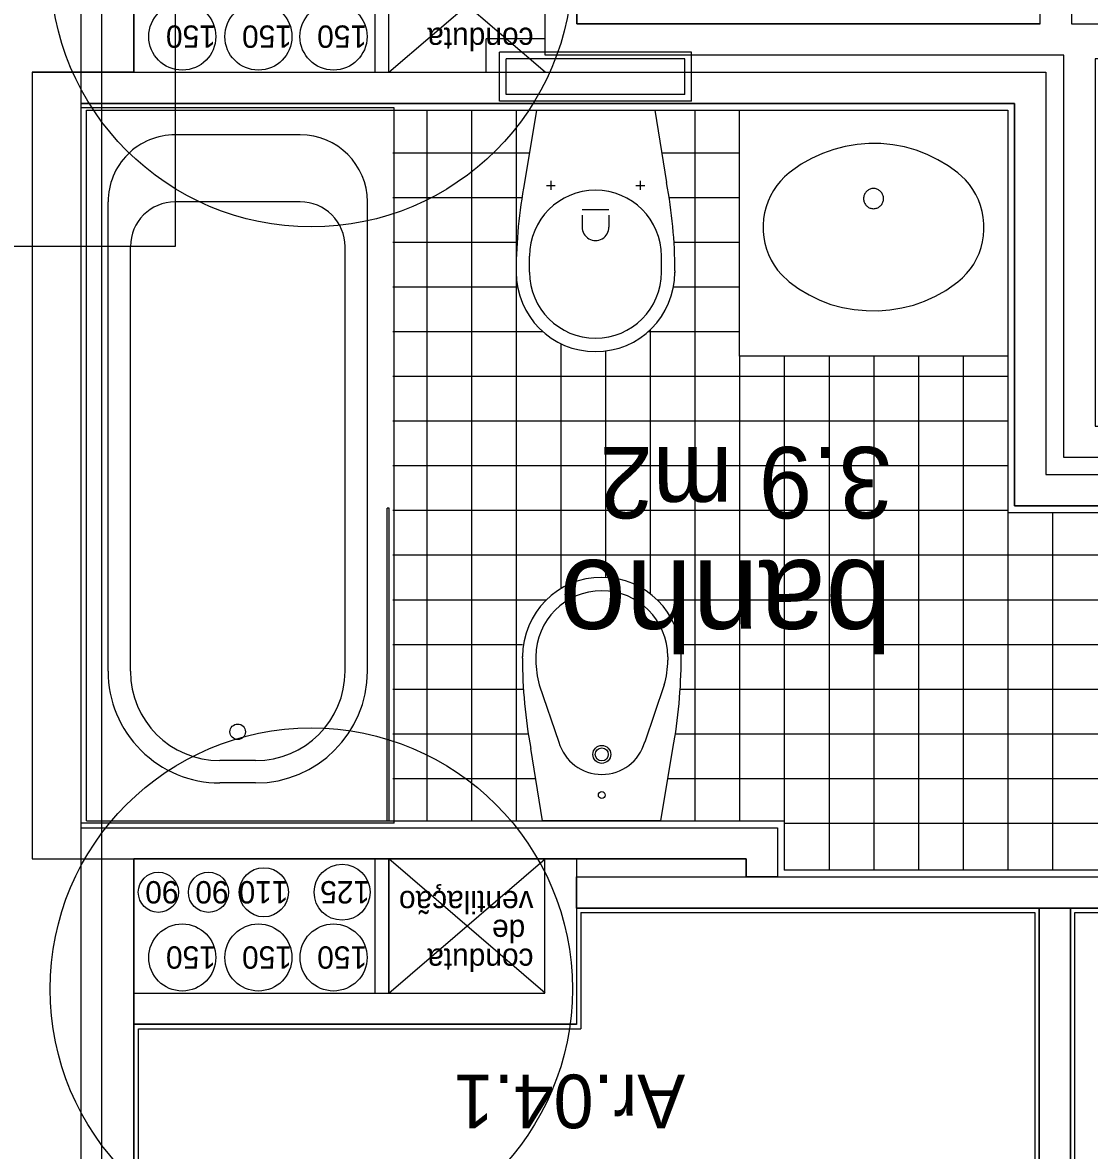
# Model space of a CAD drawing. Extents: x 1278 to 1356, y -253.7 to -224.
# Drawn here: x 1318.382 to 1320.769, y -240.956 to -238.433 of the extents above; entities that cross this region are included whole.
import ezdxf

# ---------------------------------------------------------------- set-up
doc = ezdxf.new("R2010")
doc.units = 0
for name, color, linetype in [('Level 1', 7, 'Continuous'), ('Level 10', 7, 'Continuous'), ('Level 11', 7, 'Continuous'), ('Level 2', 7, 'Continuous'), ('Level 36', 7, 'Continuous'), ('Level 40', 7, 'Continuous'), ('Level 41', 7, 'Continuous'), ('Level 60', 7, 'Continuous'), ('Level 65', 7, 'Continuous'), ('Level 66', 7, 'Continuous'), ('Level 67', 7, 'Continuous'), ('Level 69', 7, 'Continuous'), ('Level 70', 7, 'Continuous')]:
    doc.layers.add(name, color=color, linetype=linetype)

msp = doc.modelspace()

# ---------------------------------------------------------------- linework, layer by layer
at = {"layer": 'Level 1'}
for p, q in [((1320.6583, -238.4357), (1320.6583, -237.724)), ((1320.7283, -237.724), (1320.7283, -238.434)), ((1318.631, -238.544), (1318.631, -238.244)), ((1319.171, -238.544), (1319.171, -238.244)), ((1319.201, -238.544), (1319.201, -238.244)), ((1319.551, -238.499), (1319.551, -238.244)), ((1320.7283, -238.4357), (1320.8183, -238.4357)), ((1319.551, -238.469), (1319.4187, -238.469)), ((1319.551, -238.499), (1319.4487, -238.499)), ((1320.711, -238.5057), (1319.551, -238.5057)), ((1320.711, -239.4057), (1320.711, -238.5057)), ((1318.4033, -238.544), (1320.671, -238.544)), ((1320.671, -238.544), (1320.671, -239.444)), ((1318.5133, -238.614), (1320.601, -238.614)), ((1320.601, -238.614), (1320.601, -239.514)), ((1321.711, -239.4057), (1320.711, -239.4057)), ((1320.671, -239.444), (1321.671, -239.444)), ((1320.601, -239.514), (1321.601, -239.514)), ((1318.5133, -240.234), (1320.071, -240.234)), ((1320.071, -240.234), (1320.071, -240.344)), ((1318.4033, -240.304), (1319.5502, -240.304)), ((1318.631, -242.1713), (1318.631, -240.304)), ((1319.171, -240.604), (1319.171, -240.304)), ((1319.201, -240.604), (1319.201, -240.304)), ((1319.5502, -240.6039), (1319.5502, -240.3039)), ((1319.621, -240.304), (1320.001, -240.304)), ((1320.001, -240.304), (1320.001, -240.344)), ((1319.621, -240.414), (1320.656, -240.414)), ((1320.656, -240.414), (1320.656, -242.194)), ((1320.726, -242.194), (1320.726, -240.414)), ((1320.726, -240.414), (1320.836, -240.414)), ((1318.631, -240.6039), (1319.5502, -240.6039)), ((1318.6303, -240.6739), (1319.621, -240.6739))]:
    msp.add_line(p, q, dxfattribs=at)
for points in [[(1319.621, -240.304), (1319.621, -240.344)], [(1319.621, -240.414), (1319.621, -240.674)]]:
    msp.add_lwpolyline(points, dxfattribs=at)
at = {"layer": 'Level 10'}
for p, q in [((1319.286, -238.629), (1319.286, -240.219)), ((1319.386, -238.629), (1319.386, -240.219)), ((1319.486, -238.629), (1319.486, -240.219)), ((1319.886, -238.629), (1319.886, -240.219)), ((1319.2103, -238.724), (1319.5157, -238.724)), ((1319.8116, -238.724), (1319.986, -238.724)), ((1319.2103, -238.824), (1319.499, -238.824)), ((1319.8284, -238.824), (1319.986, -238.824)), ((1319.2103, -238.924), (1319.4882, -238.924)), ((1319.8393, -238.924), (1319.986, -238.924)), ((1319.2103, -239.024), (1319.4892, -239.024)), ((1319.8382, -239.024), (1319.986, -239.024)), ((1319.2103, -239.124), (1319.5456, -239.124)), ((1319.7818, -239.124), (1319.986, -239.124)), ((1319.786, -239.1201), (1319.786, -239.7109)), ((1319.586, -239.1511), (1319.586, -239.6995)), ((1319.686, -239.1676), (1319.686, -239.6742)), ((1319.986, -239.179), (1319.986, -240.219)), ((1320.086, -239.179), (1320.086, -240.219)), ((1320.186, -239.179), (1320.186, -240.329)), ((1320.286, -239.179), (1320.286, -240.329)), ((1320.386, -239.179), (1320.386, -240.329)), ((1320.486, -239.179), (1320.486, -240.329)), ((1319.2103, -239.224), (1320.586, -239.224)), ((1319.2103, -239.324), (1320.586, -239.324)), ((1319.2103, -239.424), (1320.586, -239.424)), ((1319.2103, -239.524), (1320.586, -239.524)), ((1320.586, -239.529), (1320.586, -240.329)), ((1320.686, -239.529), (1320.686, -240.329)), ((1319.2103, -239.624), (1321.586, -239.624)), ((1319.2103, -239.724), (1319.5542, -239.724)), ((1319.8012, -239.724), (1321.586, -239.724)), ((1319.2103, -239.824), (1319.5005, -239.824)), ((1319.8548, -239.824), (1321.496, -239.824)), ((1319.2103, -239.924), (1319.5024, -239.924)), ((1319.853, -239.924), (1321.496, -239.924)), ((1319.2103, -240.024), (1319.5132, -240.024)), ((1319.8422, -240.024), (1321.496, -240.024)), ((1319.2103, -240.124), (1319.5298, -240.124)), ((1319.8256, -240.124), (1321.496, -240.124)), ((1320.086, -240.224), (1321.496, -240.224))]:
    msp.add_line(p, q, dxfattribs=at)
at = {"layer": 'Level 11'}
for p, q in [((1319.4487, -238.609), (1319.4487, -238.499)), ((1319.8787, -238.499), (1319.4487, -238.499)), ((1319.8787, -238.609), (1319.8787, -238.499)), ((1319.8637, -238.514), (1319.4637, -238.514)), ((1319.4637, -238.594), (1319.4637, -238.514)), ((1319.8637, -238.594), (1319.8637, -238.514)), ((1319.8787, -238.609), (1319.4487, -238.609)), ((1319.8637, -238.594), (1319.4637, -238.594)), ((1319.2133, -238.624), (1318.5133, -238.624)), ((1318.5133, -240.224), (1318.5133, -238.624)), ((1319.2133, -240.224), (1319.2133, -238.624)), ((1319.5314, -238.629), (1319.5047, -238.791)), ((1319.5314, -238.629), (1319.796, -238.629)), ((1319.796, -238.629), (1319.8226, -238.791)), ((1319.0033, -238.684), (1318.7233, -238.684)), ((1320.2223, -238.7099), (1320.1965, -238.7166)), ((1320.2488, -238.7055), (1320.2223, -238.7099)), ((1320.2754, -238.7034), (1320.2488, -238.7055)), ((1320.3021, -238.7037), (1320.2754, -238.7034)), ((1320.3286, -238.7063), (1320.3021, -238.7037)), ((1320.3548, -238.7113), (1320.3286, -238.7063)), ((1320.3807, -238.7185), (1320.3548, -238.7113)), ((1320.147, -238.7367), (1320.1238, -238.75)), ((1320.1713, -238.7256), (1320.147, -238.7367)), ((1320.1965, -238.7166), (1320.1713, -238.7256)), ((1320.4057, -238.728), (1320.3807, -238.7185)), ((1320.4297, -238.7397), (1320.4057, -238.728)), ((1320.1238, -238.75), (1320.0967, -238.7691)), ((1320.4527, -238.7534), (1320.4297, -238.7397)), ((1320.4744, -238.7691), (1320.4527, -238.7534)), ((1319.5637, -238.7872), (1319.5637, -238.8072)), ((1319.7637, -238.7872), (1319.7637, -238.8072)), ((1320.0774, -238.7874), (1320.069, -238.7978)), ((1320.0867, -238.7779), (1320.0774, -238.7874)), ((1320.0967, -238.7691), (1320.0867, -238.7779)), ((1320.4916, -238.7851), (1320.4744, -238.7691)), ((1320.5002, -238.7953), (1320.4916, -238.7851)), ((1319.5537, -238.7972), (1319.5737, -238.7972)), ((1319.7537, -238.7972), (1319.7737, -238.7972)), ((1320.0615, -238.8089), (1320.055, -238.8206)), ((1320.069, -238.7978), (1320.0615, -238.8089)), ((1320.2685, -238.8122), (1320.2673, -238.8138)), ((1320.2698, -238.8108), (1320.2685, -238.8122)), ((1320.2712, -238.8095), (1320.2698, -238.8108)), ((1320.2728, -238.8083), (1320.2712, -238.8095)), ((1320.2744, -238.8072), (1320.2728, -238.8083)), ((1320.2761, -238.8063), (1320.2744, -238.8072)), ((1320.2779, -238.8055), (1320.2761, -238.8063)), ((1320.2798, -238.8049), (1320.2779, -238.8055)), ((1320.2817, -238.8045), (1320.2798, -238.8049)), ((1320.2836, -238.8043), (1320.2817, -238.8045)), ((1320.2855, -238.8042), (1320.2836, -238.8043)), ((1320.2875, -238.8043), (1320.2855, -238.8042)), ((1320.2894, -238.8045), (1320.2875, -238.8043)), ((1320.2913, -238.8049), (1320.2894, -238.8045)), ((1320.2932, -238.8055), (1320.2913, -238.8049)), ((1320.295, -238.8063), (1320.2932, -238.8055)), ((1320.2967, -238.8072), (1320.295, -238.8063)), ((1320.2983, -238.8083), (1320.2967, -238.8072)), ((1320.2999, -238.8095), (1320.2983, -238.8083)), ((1320.3013, -238.8108), (1320.2999, -238.8095)), ((1320.3026, -238.8122), (1320.3013, -238.8108)), ((1320.3038, -238.8138), (1320.3026, -238.8122)), ((1320.5079, -238.8062), (1320.5002, -238.7953)), ((1320.5147, -238.8177), (1320.5079, -238.8062)), ((1318.5733, -239.884), (1318.5733, -238.834)), ((1319.0033, -238.834), (1318.7233, -238.834)), ((1319.1533, -239.884), (1319.1533, -238.834)), ((1320.0495, -238.8328), (1320.0451, -238.8454)), ((1320.055, -238.8206), (1320.0495, -238.8328)), ((1320.2633, -238.8248), (1320.2632, -238.8267)), ((1320.2632, -238.8267), (1320.2633, -238.8287)), ((1320.2636, -238.8228), (1320.2633, -238.8248)), ((1320.2633, -238.8287), (1320.2636, -238.8307)), ((1320.264, -238.8209), (1320.2636, -238.8228)), ((1320.2636, -238.8307), (1320.264, -238.8326)), ((1320.2646, -238.819), (1320.264, -238.8209)), ((1320.264, -238.8326), (1320.2646, -238.8345)), ((1320.2653, -238.8172), (1320.2646, -238.819)), ((1320.2646, -238.8345), (1320.2653, -238.8363)), ((1320.2662, -238.8155), (1320.2653, -238.8172)), ((1320.2653, -238.8363), (1320.2662, -238.838)), ((1320.2673, -238.8138), (1320.2662, -238.8155)), ((1320.2662, -238.838), (1320.2673, -238.8397)), ((1320.3049, -238.8155), (1320.3038, -238.8138)), ((1320.3038, -238.8397), (1320.3049, -238.838)), ((1320.3058, -238.8172), (1320.3049, -238.8155)), ((1320.3049, -238.838), (1320.3058, -238.8363)), ((1320.3065, -238.819), (1320.3058, -238.8172)), ((1320.3058, -238.8363), (1320.3065, -238.8345)), ((1320.3071, -238.8209), (1320.3065, -238.819)), ((1320.3065, -238.8345), (1320.3071, -238.8326)), ((1320.3075, -238.8228), (1320.3071, -238.8209)), ((1320.3071, -238.8326), (1320.3075, -238.8307)), ((1320.3078, -238.8248), (1320.3075, -238.8228)), ((1320.3075, -238.8307), (1320.3078, -238.8287)), ((1320.3079, -238.8267), (1320.3078, -238.8248)), ((1320.3078, -238.8287), (1320.3079, -238.8267)), ((1320.5204, -238.8298), (1320.5147, -238.8177)), ((1320.5251, -238.8424), (1320.5204, -238.8298)), ((1319.6337, -238.8512), (1319.6937, -238.8512)), ((1319.6337, -238.8635), (1319.6337, -238.8907)), ((1319.6937, -238.8635), (1319.6937, -238.8907)), ((1320.0418, -238.8584), (1320.0396, -238.8716)), ((1320.0451, -238.8454), (1320.0418, -238.8584)), ((1320.2673, -238.8397), (1320.2685, -238.8412)), ((1320.2685, -238.8412), (1320.2698, -238.8427)), ((1320.2698, -238.8427), (1320.2712, -238.844)), ((1320.2712, -238.844), (1320.2728, -238.8452)), ((1320.2728, -238.8452), (1320.2744, -238.8463)), ((1320.2744, -238.8463), (1320.2761, -238.8472)), ((1320.2761, -238.8472), (1320.2779, -238.8479)), ((1320.2779, -238.8479), (1320.2798, -238.8485)), ((1320.2798, -238.8485), (1320.2817, -238.849)), ((1320.2817, -238.849), (1320.2836, -238.8492)), ((1320.2836, -238.8492), (1320.2855, -238.8493)), ((1320.2855, -238.8493), (1320.2875, -238.8492)), ((1320.2875, -238.8492), (1320.2894, -238.849)), ((1320.2894, -238.849), (1320.2913, -238.8485)), ((1320.2913, -238.8485), (1320.2932, -238.8479)), ((1320.2932, -238.8479), (1320.295, -238.8472)), ((1320.295, -238.8472), (1320.2967, -238.8463)), ((1320.2967, -238.8463), (1320.2983, -238.8452)), ((1320.2983, -238.8452), (1320.2999, -238.844)), ((1320.2999, -238.844), (1320.3013, -238.8427)), ((1320.3013, -238.8427), (1320.3026, -238.8412)), ((1320.3026, -238.8412), (1320.3038, -238.8397)), ((1320.5286, -238.8553), (1320.5251, -238.8424)), ((1320.5311, -238.8685), (1320.5286, -238.8553)), ((1320.0396, -238.8716), (1320.0386, -238.8863)), ((1320.0386, -238.8863), (1320.0387, -238.9001)), ((1320.5324, -238.8831), (1320.5311, -238.8685)), ((1320.5325, -238.8969), (1320.5324, -238.8831)), ((1320.0387, -238.9001), (1320.04, -238.9135)), ((1320.04, -238.9135), (1320.0425, -238.9267)), ((1320.5293, -238.9235), (1320.5315, -238.9103)), ((1320.5315, -238.9103), (1320.5325, -238.8969)), ((1318.6233, -239.884), (1318.6233, -238.934)), ((1319.1033, -239.884), (1319.1033, -238.934)), ((1320.0425, -238.9267), (1320.046, -238.9396)), ((1320.046, -238.9396), (1320.0507, -238.9521)), ((1320.5216, -238.9492), (1320.526, -238.9365)), ((1320.526, -238.9365), (1320.5293, -238.9235)), ((1319.5162, -238.9915), (1319.5162, -238.9554)), ((1319.8112, -238.9915), (1319.8112, -238.9554)), ((1320.0507, -238.9521), (1320.0564, -238.9642)), ((1320.0564, -238.9642), (1320.0632, -238.9758)), ((1320.5096, -238.9731), (1320.5161, -238.9614)), ((1320.5161, -238.9614), (1320.5216, -238.9492)), ((1319.4862, -238.9881), (1319.4862, -238.9918)), ((1319.8412, -238.9881), (1319.8412, -238.9918)), ((1320.0632, -238.9758), (1320.0709, -238.9867)), ((1320.0709, -238.9867), (1320.0795, -238.9969)), ((1320.4937, -238.9945), (1320.5021, -238.9841)), ((1320.5021, -238.9841), (1320.5096, -238.9731)), ((1320.0795, -238.9969), (1320.0967, -239.0128)), ((1320.0967, -239.0128), (1320.1184, -239.0285)), ((1320.4473, -239.032), (1320.4744, -239.0128)), ((1320.4744, -239.0128), (1320.4844, -239.0041)), ((1320.4844, -239.0041), (1320.4937, -238.9945)), ((1320.1184, -239.0285), (1320.1414, -239.0422)), ((1320.4241, -239.0452), (1320.4473, -239.032)), ((1320.1414, -239.0422), (1320.1654, -239.0539)), ((1320.1654, -239.0539), (1320.1904, -239.0634)), ((1320.1904, -239.0634), (1320.2161, -239.0706)), ((1320.3486, -239.071), (1320.3746, -239.0653)), ((1320.3746, -239.0653), (1320.3998, -239.0564)), ((1320.3998, -239.0564), (1320.4241, -239.0452)), ((1320.2161, -239.0706), (1320.2425, -239.0746)), ((1320.2425, -239.0746), (1320.269, -239.0772)), ((1320.269, -239.0772), (1320.2957, -239.0775)), ((1320.2957, -239.0775), (1320.3223, -239.0754)), ((1320.3223, -239.0754), (1320.3486, -239.071)), ((1319.5002, -239.8548), (1319.5002, -239.8512)), ((1319.5302, -239.8515), (1319.5302, -239.8596)), ((1319.8252, -239.8515), (1319.8252, -239.8596)), ((1319.8552, -239.8548), (1319.8552, -239.8512)), ((1319.5379, -239.9145), (1319.5815, -240.0424)), ((1319.8175, -239.9145), (1319.7739, -240.0424)), ((1319.5454, -240.219), (1319.5187, -240.0569)), ((1319.81, -240.219), (1319.8367, -240.0569)), ((1318.9033, -240.084), (1318.8233, -240.084)), ((1318.9033, -240.134), (1318.8233, -240.134)), ((1319.2133, -240.224), (1318.5133, -240.224)), ((1319.81, -240.219), (1319.5454, -240.219))]:
    msp.add_line(p, q, dxfattribs=at)
for centre, radius in [((1318.8633, -240.0195), 0.0173), ((1319.6777, -240.0701), 0.02), ((1319.6777, -240.0701), 0.0146), ((1319.6777, -240.161), 0.00766)]:
    msp.add_circle(centre, radius, dxfattribs=at)
for centre, radius, start, end in [((1318.7233, -238.834), 0.15, 89.9999, 180.0002), ((1319.0033, -238.834), 0.15, 360, 90), ((1319.6637, -238.9554), 0.1475, 0.0002, 179.9999), ((1318.7233, -238.934), 0.1, 90.0001, 179.9999), ((1319.0033, -238.934), 0.1, 360, 90.0001), ((1319.6637, -238.8905), 0.03, 179.9995, 0.0013), ((1319.6637, -238.9915), 0.1775, 180.0002, 359.9999), ((1319.6637, -238.9915), 0.1475, 180.0002, 359.9999), ((1319.6777, -239.8515), 0.1775, 0.0002, 179.9999), ((1319.6777, -239.8515), 0.1475, 0.0002, 179.9999), ((1319.7302, -239.8596), 0.2, 180.0017, 195.9319), ((1319.6252, -239.8596), 0.2, 344.0693, 0.0006), ((1318.8233, -239.884), 0.25, 180, 270.0001), ((1318.8233, -239.884), 0.2, 180, 270), ((1318.9033, -239.884), 0.25, 269.9999, 359.9999), ((1318.9033, -239.884), 0.2, 270, 0), ((1319.6777, -240.015), 0.1, 195.9317, 344.1953)]:
    msp.add_arc(centre, radius, start, end, dxfattribs=at)
for centre, major_axis, ratio, start_param, end_param in [((1320.8862, -238.9881), (-1.4, 0), 0.867931, 6.120269, 6.283188), ((1318.4412, -238.9881), (1.4, 0), 0.867931, 6.283184, 6.446103), ((1320.9002, -239.8549), (-1.4, 0), 0.88995, 6.283183, 6.446102), ((1318.4552, -239.8549), (1.4, 0), 0.88995, 6.120269, 6.283187)]:
    msp.add_ellipse(centre, major_axis=major_axis, ratio=ratio, start_param=start_param, end_param=end_param, dxfattribs=at)
at = {"layer": 'Level 2'}
for p, q in [((1319.986, -239.179), (1319.986, -238.629)), ((1320.586, -238.629), (1320.586, -239.179)), ((1320.586, -239.179), (1319.986, -239.179))]:
    msp.add_line(p, q, dxfattribs=at)
at = {"layer": 'Level 36'}
for p, q in [((1319.2023, -239.519), (1319.1973, -239.519)), ((1319.1973, -240.219), (1319.1973, -239.519)), ((1319.2023, -240.219), (1319.2023, -239.519))]:
    msp.add_line(p, q, dxfattribs=at)
at = {"layer": 'Level 41'}
for p, q in [((1319.551, -238.544), (1319.201, -238.244)), ((1319.201, -238.544), (1319.551, -238.244)), ((1319.551, -240.604), (1319.201, -240.304)), ((1319.201, -240.604), (1319.551, -240.304))]:
    msp.add_line(p, q, dxfattribs=at)
for centre, radius in [((1318.7393, -238.4644), 0.075), ((1318.9095, -238.4644), 0.075), ((1319.0775, -238.4644), 0.075), ((1318.9218, -240.3785), 0.055), ((1319.0967, -240.3785), 0.0625), ((1318.6858, -240.3785), 0.045), ((1318.7978, -240.3785), 0.045), ((1318.7393, -240.5244), 0.075), ((1318.9095, -240.5244), 0.075), ((1319.0776, -240.5244), 0.075)]:
    msp.add_circle(centre, radius, dxfattribs=at)
at = {"layer": 'Level 65'}
for p, q in [((1318.5253, -240.219), (1318.5253, -238.629)), ((1318.5253, -238.629), (1320.586, -238.629)), ((1320.586, -238.629), (1320.586, -239.529)), ((1320.586, -239.529), (1321.586, -239.529)), ((1318.5253, -240.219), (1320.086, -240.219)), ((1320.086, -240.219), (1320.086, -240.329)), ((1320.836, -240.329), (1320.086, -240.329)), ((1319.631, -240.424), (1320.646, -240.424)), ((1320.646, -240.424), (1320.646, -242.194)), ((1320.736, -242.194), (1320.736, -240.424)), ((1320.736, -240.424), (1320.836, -240.424)), ((1318.641, -240.6839), (1319.631, -240.6839)), ((1318.641, -242.029), (1318.641, -240.6839))]:
    msp.add_line(p, q, dxfattribs=at)
msp.add_lwpolyline([(1319.631, -240.424), (1319.631, -240.6839)], dxfattribs=at)
at = {"layer": 'Level 66'}
for p, q in [((1319.6218, -238.4357), (1319.6218, -238.174)), ((1318.5133, -238.544), (1318.5133, -238.244)), ((1320.6583, -238.4357), (1319.6218, -238.4357)), ((1319.4187, -238.544), (1319.4187, -238.469)), ((1319.4487, -238.544), (1319.4487, -238.499)), ((1319.551, -238.5057), (1319.551, -238.499)), ((1318.4033, -238.544), (1318.4033, -240.304)), ((1318.5133, -242.1713), (1318.5133, -238.544)), ((1319.621, -240.344), (1320.001, -240.344)), ((1320.071, -240.344), (1320.836, -240.344))]:
    msp.add_line(p, q, dxfattribs=at)
at = {"layer": 'Level 67'}
for points in [[(1320.7283, -237.724), (1320.7283, -238.4357), (1320.8183, -238.4357), (1320.8183, -238.514), (1320.781, -238.514), (1320.781, -239.3357), (1321.781, -239.3357), (1321.781, -240.234), (1323.801, -240.234), (1323.801, -240.304), (1321.711, -240.304), (1321.711, -239.4057), (1320.711, -239.4057), (1320.711, -238.5057), (1319.551, -238.5057), (1319.551, -238.244)], [(1319.6218, -238.174), (1319.6218, -238.4357), (1320.6583, -238.4357), (1320.6583, -237.724)], [(1318.631, -238.244), (1318.631, -238.544), (1318.5133, -238.544), (1318.5133, -238.244)]]:
    msp.add_lwpolyline(points, dxfattribs=at)
for points in [[(1318.4033, -240.304), (1318.5133, -240.304), (1318.5133, -238.544), (1318.4033, -238.544)], [(1323.801, -240.414), (1321.566, -240.414), (1321.566, -240.334), (1321.601, -240.334), (1321.601, -239.514), (1320.601, -239.514), (1320.601, -238.614), (1318.5133, -238.614), (1318.5133, -238.544), (1320.671, -238.544), (1320.671, -239.444), (1321.671, -239.444), (1321.671, -240.344), (1323.801, -240.344)], [(1318.631, -242.1713), (1318.5133, -242.1713), (1318.5133, -240.234), (1320.071, -240.234), (1320.071, -240.344), (1320.001, -240.344), (1320.001, -240.304), (1318.631, -240.304)], [(1319.621, -240.304), (1319.621, -240.6739), (1318.631, -240.6739), (1318.631, -240.6039), (1319.171, -240.6039), (1319.171, -240.304), (1319.201, -240.304), (1319.201, -240.604), (1319.5502, -240.604), (1319.5502, -240.3039)], [(1320.836, -240.414), (1319.621, -240.414), (1319.621, -240.344), (1320.836, -240.344)], [(1320.726, -240.414), (1320.726, -242.194), (1320.656, -242.194), (1320.656, -240.414)]]:
    msp.add_lwpolyline(points, close=True, dxfattribs=at)
at = {"layer": 'Level 69'}
msp.add_lwpolyline([(1318.7233, -238.934), (1315.3724, -238.934), (1315.3724, -236.4315), (1318.7233, -236.4315)], close=True, dxfattribs=at)
for centre in [(1319.0278, -238.3059), (1319.0278, -240.5951)]:
    msp.add_circle(centre, 0.5842, dxfattribs=at)
at = {"layer": 'Level 70'}
msp.add_line((1318.5594, -250.7923), (1318.5594, -229.6198), dxfattribs=at)

# ---------------------------------------------------------------- texts
at = {"layer": 'Level 40'}
msp.add_text('Ar.04.1', height=0.12, rotation=180, dxfattribs=at).set_placement((1319.8642, -240.7863))
at = {"layer": 'Level 41'}
for s, p in [('150', (1318.8143, -238.4394)), ('150', (1318.9845, -238.4394)), ('150', (1319.1525, -238.4394)), ('conduta', (1319.525, -238.4444)), ('90', (1318.7308, -240.3535)), ('90', (1318.8428, -240.3535)), ('110', (1318.9768, -240.3535)), ('125', (1319.1592, -240.3535)), ('ventilação ', (1319.525, -240.3755)), (' de ', (1319.525, -240.4399)), ('150', (1318.8143, -240.4994)), ('150', (1318.9845, -240.4994)), ('150', (1319.1526, -240.4994)), ('conduta', (1319.525, -240.5044))]:
    msp.add_text(s, height=0.05, rotation=180, dxfattribs=at).set_placement(p)
at = {"layer": 'Level 60'}
for s, height, p in [('3.9 m2', 0.16, (1320.327, -239.3821)), ('banho', 0.2, (1320.3267, -239.6356))]:
    msp.add_text(s, height=height, rotation=180, dxfattribs=at).set_placement(p)

doc.saveas('drawing.dxf')
